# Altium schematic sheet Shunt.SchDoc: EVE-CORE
size A4; Organization: Ingenia Motion Control; Address1: Carrer Avila, 124, 2B; Address2: 08018 Barcelona Spain; Address3: www.ingeniamc.com; Address4: www.ingeniamc.com; Documentation: https://doc.ingeniamc.com/x/coAZBg
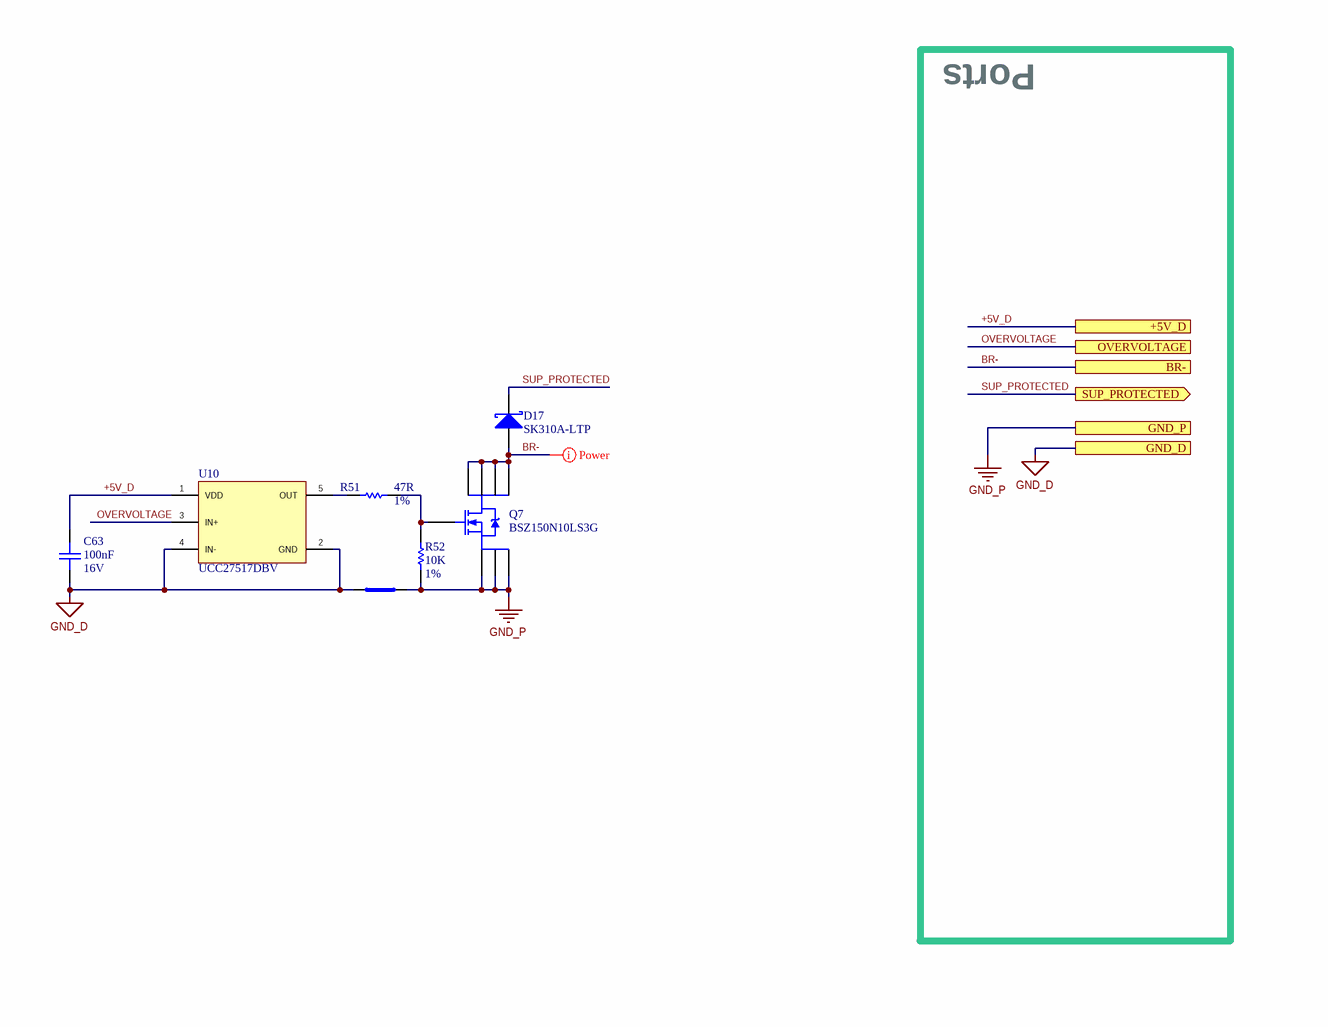
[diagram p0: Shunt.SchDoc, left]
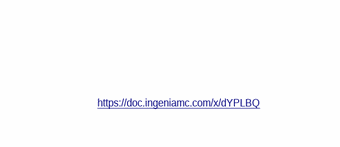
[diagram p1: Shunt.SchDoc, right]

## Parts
C63  value 100nF  Voltage: 16V  [C_0402]  (hidden comment: C_0402--100nF--16V)
D17  SK310A-LTP  [HSMA/DO-214AC]
NT2  NT2x1608  [NETTIE-SMT-1608]  (value not drawn)  (net tie, no BOM)
Q7  BSZ150N10LS3G  [TSDSON-8]
R51  value 47R  Tolerance: 1%  [R_0402]  (hidden comment: R_0402--47R--1%)
R52  value 10K  Tolerance: 1%  [R_0402]  (hidden comment: R_0402--10K--1%)
U10  UCC27517DBV  [SOT23-5N]

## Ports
+5V_D, BR-, GND_D, GND_P, OVERVOLTAGE, SUP_PROTECTED (out)

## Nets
GND_D: C63.2 NT2.1(Net1) U10.2(GND) U10.4(IN-) ; port GND_D
GND_P: NT2.2(Net2) Q7.1(S) Q7.2(S) Q7.3(S) R52.2 ; port GND_P
+5V_D: C63.1 U10.1(VDD) ; port +5V_D
BR-: D17.1(A) Q7.5(D) Q7.6(D) Q7.7(D) Q7.8(D) ; port BR-
OVERVOLTAGE: U10.3(IN+) ; port OVERVOLTAGE
SUP_PROTECTED: D17.2(K) ; port SUP_PROTECTED
NetQ7_4: Q7.4(G) R51.2 R52.1
NetR51_1: R51.1 U10.5(OUT)

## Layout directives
net class Power: BR-

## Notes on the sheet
- Ports
- https://doc.ingeniamc.com/x/dYPLBQ

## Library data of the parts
C63 = C_0402[[/\]]100nF[[/\]]16V: CAP CER 100nF 16V X7R 0402; ManufacturerName: Murata; ManufacturerPN: GRM155R71C104KA88D; AlternativeManufacturer: Wurth; IsPreferred: 1; IngeniaID: 672; InternalStock: 0; TemperatureMaxC: 125; TemperatureMinC: -55; MTBF55h: 36129613; AlternativePN: 885012205037
D17 = SK310A-LTP: DIODE Schottky 3 A 100 V, SMA; ManufacturerName: Micro Commercial Co; Value: 100V; IsPreferred: 0; IngeniaID: 3665; TemperatureMaxC: 125; TemperatureMinC: -50
NT2 = NT2x1608: Net-Tie, Surface Mount, 2 x 1.6mm x 0.8mm SMT Pads; ManufacturerName: Ingenia; ManufacturerPN: 8; IsPreferred: 0; IngeniaID: 465
Q7 = BSZ150N10LS3G: MOSFET N-CH 100V 40A 15mohm logic level TSDSON-8; ManufacturerName: Infineon; IsPreferred: 0; IngeniaID: 3106
R51 = R_0402[[/\]]47R[[/\]]1%: RES 47 OHM 1/8W 1% 0402 SMD; ManufacturerName: Vishay Draloric; ManufacturerPN: CRCW040247R0FKEDHP; AlternativeManufacturer: Panasonic; IsPreferred: 0; IsGeneric: 1; IngeniaID: 750; TemperatureMaxC: 155; TemperatureMinC: -55; AlternativePN: ERJ-PA2F47R0X
R52 = R_0402[[/\]]10K[[/\]]1%: RESISTOR 10K OHM 1/16W 1% 0402 SMD; ManufacturerName: Stackpole Electronics; ManufacturerPN: RMCF0402FT10K0; AlternativeManufacturer: Vishay Dale; IsPreferred: 0; IsGeneric: 1; IngeniaID: 685; TemperatureMaxC: 155; TemperatureMinC: -55; MTBF55h: 91649788; AlternativePN: CRCW040210K0FKED
U10 = UCC27517DBV: IC GATE DRIVER MOSFET, 4A PEAK, LOW SIDE, SOT23-5; ManufacturerName: Texas Instruments; ManufacturerPN: UCC27517DBVT; IsPreferred: 1; IsGeneric: 0; IngeniaID: 2077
